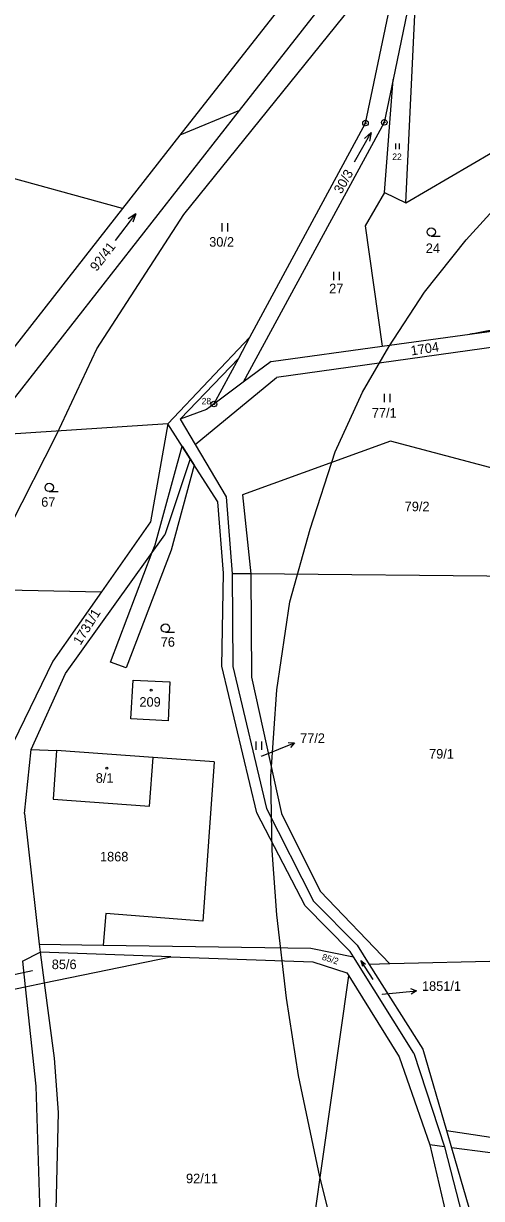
# Model space of a CAD drawing. Extents: x -546762 to -540209, y -1046851 to -1035694.
# Drawn here: x -543686.9 to -543605.4, y -1041018.4 to -1040809.1 of the extents above; entities that cross this region are included whole.
import ezdxf

# ---------------------------------------------------------------- set-up
doc = ezdxf.new("R2010")
doc.units = 0
for name, color, linetype in [('Vrstva 1', 7, 'Continuous'), ('Vrstva 16', 7, 'Continuous'), ('Vrstva 18', 7, 'Continuous'), ('Vrstva 19', 7, 'Continuous'), ('Vrstva 24', 7, 'Continuous'), ('Vrstva 25', 7, 'Continuous'), ('Vrstva 3', 7, 'Continuous'), ('Vrstva 30', 7, 'Continuous'), ('Vrstva 37', 7, 'Continuous'), ('Vrstva 52', 7, 'Continuous'), ('Vrstva 6', 7, 'Continuous')]:
    doc.layers.add(name, color=color, linetype=linetype)

msp = doc.modelspace()

# ---------------------------------------------------------------- linework, layer by layer
at = {"layer": 'Vrstva 1'}
for points in [[(-543614.55, -1040772.16), (-543659.09, -1040828.98)], [(-543612.86, -1040779.08), (-543621.09, -1040819.02)], [(-543648.44, -1040824.55), (-543617.16, -1040784.58)], [(-543626.02, -1040826.79), (-543617.16, -1040784.58)], [(-543618.82, -1040841.02), (-543617.05, -1040803.71)], [(-543621.09, -1040819.02), (-543622.67, -1040826.68)], [(-543622.62, -1040839.15), (-543621.09, -1040819.02)], [(-543691.97, -1040880.16), (-543648.44, -1040824.55)], [(-543622.67, -1040826.68), (-543647.79, -1040872.97)], [(-543646.6, -1040864.93), (-543626.02, -1040826.79)], [(-543618.82, -1040841.02), (-543595.67, -1040827.46)], [(-543659.09, -1040828.98), (-543669.32, -1040842.04)], [(-543669.32, -1040842.04), (-543693.52, -1040835.34)], [(-543622.62, -1040839.15), (-543626.09, -1040845.12)], [(-543622.62, -1040839.15), (-543618.82, -1040841.02)], [(-543669.32, -1040842.04), (-543699.55, -1040880.61)], [(-543626.09, -1040845.12), (-543623.05, -1040866.57)], [(-543623.05, -1040866.57), (-543595.75, -1040862.83)], [(-543646.6, -1040864.93), (-543661.22, -1040880.35)], [(-543648.61, -1040868.66), (-543646.6, -1040864.93)], [(-543597.23, -1040865.88), (-543641.89, -1040872.11)], [(-543642.8, -1040869.28), (-543623.05, -1040866.57)], [(-543653.03, -1040876.85), (-543648.61, -1040868.66)], [(-543642.8, -1040869.28), (-543647.79, -1040872.97)], [(-543656.36, -1040884.04), (-543641.89, -1040872.11)], [(-543647.79, -1040872.97), (-543653.03, -1040876.85)], [(-543653.03, -1040876.85), (-543654.32, -1040877.8)], [(-543654.32, -1040877.8), (-543659.01, -1040879.53)], [(-543661.22, -1040880.35), (-543693.82, -1040882.53)], [(-543661.22, -1040880.35), (-543664.3, -1040897.83)], [(-543657.23, -1040886.62), (-543661.22, -1040880.35)], [(-543659.01, -1040879.53), (-543656.36, -1040884.04)], [(-543656.36, -1040884.04), (-543650.87, -1040893.38)], [(-543621.58, -1040883.48), (-543647.91, -1040893.03)], [(-543596.04, -1040890.24), (-543621.58, -1040883.48)], [(-543657.23, -1040886.62), (-543661.78, -1040900.14)], [(-543652.35, -1040894.27), (-543657.23, -1040886.62)], [(-543650.87, -1040893.38), (-543649.75, -1040907.08)], [(-543647.91, -1040893.03), (-543646.42, -1040907.11)], [(-543651.31, -1040906.97), (-543652.35, -1040894.27)], [(-543664.3, -1040897.83), (-543673.05, -1040910.3)], [(-543679.49, -1040924.85), (-543661.78, -1040900.14)], [(-543651.59, -1040923.53), (-543651.31, -1040906.97)], [(-543649.75, -1040907.08), (-543649.64, -1040923.59)], [(-543646.42, -1040907.11), (-543649.75, -1040907.08)], [(-543646.42, -1040907.11), (-543646.32, -1040925.49)], [(-543598.38, -1040907.55), (-543646.42, -1040907.11)], [(-543704.16, -1040909.66), (-543673.05, -1040910.3)], [(-543673.05, -1040910.3), (-543681.72, -1040922.67)], [(-543681.72, -1040922.67), (-543690.83, -1040941.37)], [(-543685.55, -1040938.37), (-543679.49, -1040924.85)], [(-543645.35, -1040949.68), (-543651.59, -1040923.53)], [(-543649.64, -1040923.59), (-543643.67, -1040948.9)], [(-543667.81, -1040932.94), (-543667.39, -1040926.05)], [(-543667.39, -1040926.05), (-543660.89, -1040926.37)], [(-543660.89, -1040926.37), (-543661.19, -1040933.26)], [(-543646.32, -1040925.49), (-543640.98, -1040949.77)], [(-543661.19, -1040933.26), (-543667.81, -1040932.94)], [(-543686.78, -1040949.8), (-543685.55, -1040938.37)], [(-543685.55, -1040938.37), (-543681.05, -1040938.58)], [(-543681.05, -1040938.58), (-543681.68, -1040947.27)], [(-543663.87, -1040939.83), (-543681.05, -1040938.58)], [(-543664.47, -1040948.52), (-543663.87, -1040939.83)], [(-543652.97, -1040940.6), (-543663.87, -1040939.83)], [(-543652.97, -1040940.6), (-543655, -1040969)], [(-543681.68, -1040947.27), (-543664.47, -1040948.52)], [(-543686.78, -1040949.8), (-543684.15, -1040973.06)], [(-543636.78, -1040966.24), (-543645.35, -1040949.68)], [(-543643.67, -1040948.9), (-543635.28, -1040965.41)], [(-543640.98, -1040949.77), (-543634.11, -1040963.64)], [(-543634.11, -1040963.64), (-543621.68, -1040976.59)], [(-543628.77, -1040974.37), (-543636.78, -1040966.24)], [(-543635.28, -1040965.41), (-543627.52, -1040973.26)], [(-543672.3, -1040967.62), (-543672.74, -1040973.23)], [(-543655, -1040969), (-543672.3, -1040967.62)], [(-543684.15, -1040973.06), (-543683.99, -1040974.51)], [(-543684.15, -1040973.06), (-543672.74, -1040973.23)], [(-543687.11, -1040976.1), (-543683.99, -1040974.51)], [(-543672.74, -1040973.23), (-543635.74, -1040973.78)], [(-543635.74, -1040973.78), (-543628.18, -1040975.31)], [(-543628.18, -1040975.31), (-543628.77, -1040974.37)], [(-543617.4, -1040992.47), (-543628.18, -1040975.31)], [(-543627.52, -1040973.26), (-543625.36, -1040976.68)], [(-543683.27, -1040979.99), (-543660.69, -1040975.32)], [(-543660.69, -1040975.32), (-543635.43, -1040976.2)], [(-543635.43, -1040976.2), (-543629.34, -1040978.2)], [(-543621.68, -1040976.59), (-543625.36, -1040976.68)], [(-543625.36, -1040976.68), (-543615.81, -1040991.77)], [(-543580.97, -1040975.6), (-543621.68, -1040976.59)], [(-543639.72, -1041054.36), (-543629.01, -1040978.73)], [(-543629.34, -1040978.2), (-543629.01, -1040978.73)], [(-543629.01, -1040978.73), (-543620.04, -1040993.13)], [(-543726.55, -1040988.94), (-543686.62, -1040980.68)], [(-543686.62, -1040980.68), (-543683.27, -1040979.99)], [(-543615.81, -1040991.77), (-543611.59, -1041006.29)], [(-543620.04, -1040993.13), (-543614.56, -1041008.83)], [(-543617.4, -1040992.47), (-543611.97, -1041009.17)], [(-543611.59, -1041006.29), (-543610.7, -1041009.33)], [(-543611.59, -1041006.29), (-543579.59, -1041011.06)], [(-543614.56, -1041008.83), (-543609.14, -1041031.96)], [(-543611.97, -1041009.17), (-543614.56, -1041008.83)], [(-543611.97, -1041009.17), (-543608.24, -1041023.49)], [(-543610.7, -1041009.33), (-543606.53, -1041023.67)], [(-543597.75, -1041011.03), (-543610.7, -1041009.33)]]:
    msp.add_lwpolyline(points, dxfattribs=at)
at = {"layer": 'Vrstva 16'}
for p, q in [((-543641.45, -1040938.34), (-543638.67, -1040937.22)), ((-543619.95, -1040981.68), (-543616.96, -1040981.39))]:
    msp.add_line(p, q, dxfattribs=at)
for points in [[(-543639.78, -1040937.13), (-543638.67, -1040937.22), (-543639.41, -1040938.06)], [(-543644.56, -1040939.59), (-543641.45, -1040938.34)], [(-543685.34, -1040977.85), (-543689.21, -1040978.67)], [(-543618.01, -1040980.99), (-543616.96, -1040981.39), (-543617.91, -1040981.98)], [(-543623.04, -1040981.99), (-543619.95, -1040981.68)]]:
    msp.add_lwpolyline(points, dxfattribs=at)
at = {"layer": 'Vrstva 24'}
for centre, radius in [((-543626.02, -1040826.79), 0.5), ((-543626.02, -1040826.79), 0.1), ((-543622.67, -1040826.68), 0.5), ((-543622.67, -1040826.68), 0.1), ((-543653.03, -1040876.85), 0.5), ((-543653.03, -1040876.85), 0.1)]:
    msp.add_circle(centre, radius, dxfattribs=at)
at = {"layer": 'Vrstva 25'}
for p, q in [((-543620.6, -1040831.44), (-543620.6, -1040830.44)), ((-543619.94, -1040831.44), (-543619.94, -1040830.44)), ((-543651.55, -1040846.12), (-543651.55, -1040844.62)), ((-543650.55, -1040846.12), (-543650.55, -1040844.62)), ((-543614.3, -1040846.95), (-543612.7, -1040846.95)), ((-543631.65, -1040854.78), (-543631.65, -1040853.28)), ((-543630.65, -1040854.78), (-543630.65, -1040853.28)), ((-543622.61, -1040876.52), (-543622.61, -1040875.02)), ((-543621.61, -1040876.52), (-543621.61, -1040875.02)), ((-543682.35, -1040892.45), (-543680.75, -1040892.45)), ((-543661.66, -1040917.51), (-543660.06, -1040917.51)), ((-543645.48, -1040938.45), (-543645.48, -1040936.95)), ((-543644.48, -1040938.45), (-543644.48, -1040936.95))]:
    msp.add_line(p, q, dxfattribs=at)
for points in [[(-543627.95, -1040833.72), (-543625.01, -1040828.5), (-543626.18, -1040829.56)], [(-543625.01, -1040828.5), (-543625.31, -1040830.05)], [(-543670.58, -1040847.74), (-543666.96, -1040842.96), (-543668.27, -1040843.85)], [(-543666.96, -1040842.96), (-543667.47, -1040844.45)], [(-543624.67, -1040979.35), (-543626.83, -1040975.97), (-543626.57, -1040976.99)], [(-543626.83, -1040975.97), (-543626.01, -1040976.63)]]:
    msp.add_lwpolyline(points, dxfattribs=at)
for centre, radius in [((-543614.3, -1040846.2), 0.75), ((-543682.35, -1040891.7), 0.75), ((-543661.66, -1040916.76), 0.75), ((-543664.21, -1040927.85), 0.175), ((-543672.11, -1040941.72), 0.175)]:
    msp.add_circle(centre, radius, dxfattribs=at)
at = {"layer": 'Vrstva 3'}
for points in [[(-543667.81, -1040932.94), (-543667.39, -1040926.05)], [(-543667.39, -1040926.05), (-543660.89, -1040926.37)], [(-543660.89, -1040926.37), (-543661.19, -1040933.26)], [(-543661.19, -1040933.26), (-543667.81, -1040932.94)], [(-543681.05, -1040938.58), (-543681.68, -1040947.27)], [(-543663.87, -1040939.83), (-543681.05, -1040938.58)], [(-543664.47, -1040948.52), (-543663.87, -1040939.83)], [(-543681.68, -1040947.27), (-543664.47, -1040948.52)]]:
    msp.add_lwpolyline(points, dxfattribs=at)
at = {"layer": 'Vrstva 30'}
for points in [[(-543607.46, -1040864.43), (-543600.82, -1040863.08), (-543588.43, -1040859.98), (-543585.17, -1040858.46), (-543582.38, -1040857.15), (-543577.26, -1040854.74), (-543581.9, -1040858.06), (-543584.85, -1040859.07), (-543595.75, -1040862.83), (-543607.46, -1040864.43)], [(-543671.43, -1040922.81), (-543664.01, -1040903.24), (-543663.51, -1040901.94), (-543658.65, -1040884.38), (-543657.23, -1040886.62), (-543656.52, -1040887.73), (-543660.65, -1040902.86), (-543668.63, -1040923.87), (-543671.43, -1040922.81)]]:
    msp.add_lwpolyline(points, dxfattribs=at)
at = {"layer": 'Vrstva 37'}
for centre in [(-543664.21, -1040927.85), (-543672.11, -1040941.72)]:
    msp.add_circle(centre, 0.175, dxfattribs=at)
at = {"layer": 'Vrstva 52'}
for points in [[(-543761.66, -1041076.07), (-543723.84, -1040985.67), (-543700.74, -1040927.15), (-543689.29, -1040898.52), (-543681.03, -1040882.19), (-543673.88, -1040867.03), (-543658.41, -1040843.09), (-543543.36, -1040700.5), (-543528.22, -1040680.75), (-543518.29, -1040668.51), (-543511.51, -1040659.9), (-543507.03, -1040652.27), (-543503.28, -1040645), (-543500.61, -1040638.09), (-543498.55, -1040630.94), (-543496.98, -1040624.64), (-543496.13, -1040618.22), (-543495.53, -1040611.92), (-543495.65, -1040606.47), (-543496.57, -1040596.65)], [(-543629.5, -1041032.97), (-543634.16, -1041014.52), (-543637.98, -1040996.49), (-543640.1, -1040982.71), (-543641.81, -1040967.83), (-543642.65, -1040956.38), (-543642.87, -1040943.23), (-543641.81, -1040927.75), (-543639.47, -1040912.06), (-543635.87, -1040899.12), (-543631.42, -1040885.34), (-543626.55, -1040874.74), (-543621.88, -1040866.68), (-543615.53, -1040856.92), (-543608.11, -1040847.59), (-543600.85, -1040839.67), (-543590.43, -1040829.62), (-543581.23, -1040821.98), (-543573.84, -1040817.26), (-543568.03, -1040814.59), (-543562.82, -1040812.53), (-543557.86, -1040811.32), (-543552.65, -1040810.71), (-543547.08, -1040810.83)]]:
    msp.add_lwpolyline(points, dxfattribs=at)
at = {"layer": 'Vrstva 6'}
for points in [[(-543648.44, -1040824.55), (-543659.09, -1040828.98)], [(-543659.01, -1040879.53), (-543648.61, -1040868.66)], [(-543660.69, -1040975.32), (-543683.99, -1040974.51)], [(-543683.99, -1040974.51), (-543683.27, -1040979.99)], [(-543687.11, -1040976.1), (-543686.62, -1040980.68)], [(-543686.62, -1040980.68), (-543684.73, -1040998.35)], [(-543683.27, -1040979.99), (-543681.51, -1040993.4)], [(-543681.51, -1040993.4), (-543680.74, -1041003.04)], [(-543684.73, -1040998.35), (-543684.03, -1041021.16)], [(-543680.74, -1041003.04), (-543681.35, -1041027.84)]]:
    msp.add_lwpolyline(points, dxfattribs=at)

# ---------------------------------------------------------------- texts
at = {"layer": 'Vrstva 16'}
for s, p in [('77/2', (-543637.67, -1040937.22)), ('1851/1', (-543615.96, -1040981.39))]:
    msp.add_text(s, height=1.7, dxfattribs=at).set_placement(p)
at = {"layer": 'Vrstva 18'}
for s, height, p in [('22', 1.14, (-543621.25, -1040833.36)), ('30/2', 1.7, (-543653.86, -1040848.82)), ('24', 1.7, (-543615.28, -1040849.95)), ('27', 1.7, (-543632.49, -1040857.13)), ('28', 1.14, (-543655.21, -1040876.9)), ('77/1', 1.7, (-543624.89, -1040879.28)), ('67', 1.7, (-543683.79, -1040895.15)), ('79/2', 1.7, (-543619.04, -1040895.95)), ('76', 1.7, (-543662.5, -1040920.09)), ('77/2', 0.1, (-543644.71, -1040939.59)), ('79/1', 1.7, (-543614.69, -1040940.01)), ('1868', 1.7, (-543673.32, -1040958.33)), ('85/6', 1.7, (-543681.91, -1040977.52)), ('85/5', 0.1, (-543685.49, -1040977.85)), ('1851/1', 0.1, (-543623.22, -1040981.99)), ('92/11', 1.7, (-543657.99, -1041015.66))]:
    msp.add_text(s, height=height, dxfattribs=at).set_placement(p)
for s, height, rotation, p in [('30/3', 1.7, 60.5973, (-543630.3, -1040839.54)), ('92/41', 1.7, 52.3147, (-543673.92, -1040853.34)), ('1704', 1.7, 8.6884, (-543617.83, -1040868.21)), ('1731/1', 1.7, 58.215, (-543676.79, -1040919.92)), ('85/2', 1.14, 342.1673, (-543633.86, -1040975.82))]:
    msp.add_text(s, height=height, rotation=rotation, dxfattribs=at).set_placement(p)
at = {"layer": 'Vrstva 19'}
for s, p in [('209', (-543666.29, -1040930.77)), ('8/1', (-543674.07, -1040944.32))]:
    msp.add_text(s, height=1.7, dxfattribs=at).set_placement(p)

doc.saveas('drawing.dxf')
